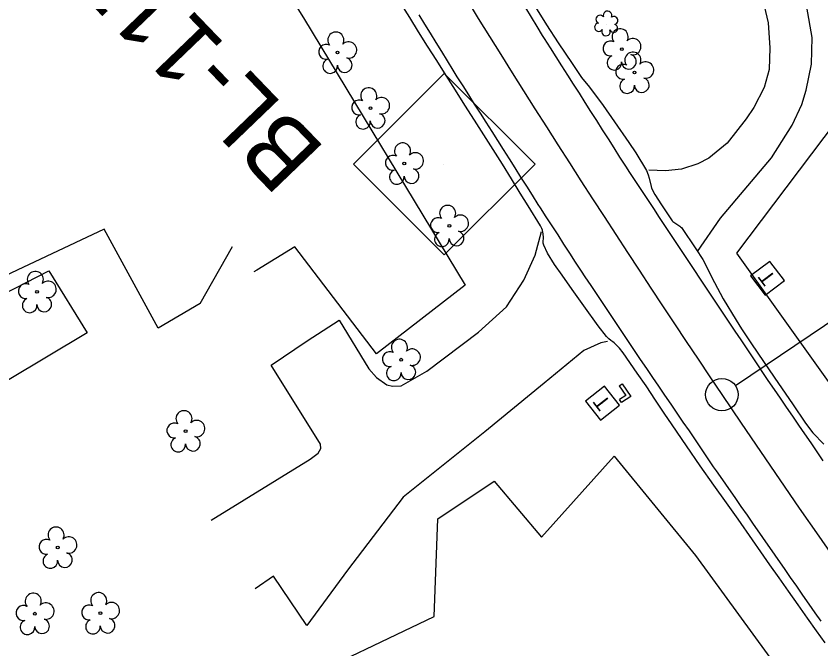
# Model space of a CAD drawing. Extents: x 474972 to 479313, y 498315 to 502691.
# Drawn here: x 476078.1 to 476264.1, y 501147 to 501293.2 of the extents above; entities that cross this region are included whole.
import ezdxf

# ---------------------------------------------------------------- set-up
doc = ezdxf.new("R2010")
doc.units = 0
for name, color, linetype in [('CTL Secondary Horizontal and Vertical CELL', 7, 'Continuous'), ('CTL Secondary Horizontal and Vertical Text', 7, 'Continuous'), ('Exist Horizontal Alignment', 7, 'Continuous'), ('Exist Other Culture Fence Line', 7, 'Continuous'), ('Exist Other Culture Gate', 7, 'Continuous'), ('Exist Roads EOP', 7, 'Continuous'), ('Exist Roads EOP Other', 7, 'Continuous'), ('Exist Roads EOT', 7, 'Continuous'), ('Exist Roads Soil', 7, 'Continuous'), ('Exist Structure Minor Head and End Wall', 7, 'Continuous'), ('Exist Utilities Telephone Pedestal CELL', 7, 'Continuous'), ('Exist Vegetation Hedge Row', 7, 'Continuous'), ('Exist Vegetation Shrub CELL', 7, 'Continuous'), ('Exist Vegetation Tree CELL', 7, 'Continuous'), ('Exist Vegetation Woods Line', 7, 'Continuous')]:
    doc.layers.add(name, color=color, linetype=linetype)

msp = doc.modelspace()

# ---------------------------------------------------------------- linework, layer by layer
at = {"layer": 'CTL Secondary Horizontal and Vertical CELL'}
msp.add_line((476176.94, 501258.94), (476176.94, 501258.94), dxfattribs=at)
msp.add_lwpolyline([(476156.08, 501259.01), (476177.05, 501279.98), (476198.05, 501258.97), (476177.08, 501238.01)], close=True, dxfattribs=at)
at = {"layer": 'Exist Horizontal Alignment'}
msp.add_line((476244.33, 501207.83), (476343.85, 501274.95), dxfattribs=at)
msp.add_circle((476241.22, 501205.74), 3.75, dxfattribs=at)
for centre, radius, start, end in [((478549.74, 502762.69), 2784.48, 207.50231, 213.99726), ((478672.62, 502845.57), 2932.7, 213.99726, 223.91157)]:
    msp.add_arc(centre, radius, start, end, dxfattribs=at)
at = {"layer": 'Exist Other Culture Fence Line'}
for points in [[(476004.79, 501280.8), (476008.93, 501283.23), (476010.34, 501284.2), (476101.32, 501347.12), (476102.6, 501347.94), (476107.45, 501351.2), (476111.31, 501345.57), (476144.53, 501292.8), (476181.9, 501231.04), (476161.39, 501215.16), (476142.53, 501239.91), (476133.73, 501234.48)], [(476120.67, 501226.83), (476110.96, 501221.14), (476098.44, 501243.97), (476039.4, 501216.16), (476004.79, 501280.8)], [(476133.73, 501234.48), (476133.1, 501234.11)]]:
    msp.add_lwpolyline(points, dxfattribs=at)
at = {"layer": 'Exist Other Culture Gate'}
msp.add_line((476120.67, 501226.83), (476128.16, 501239.99), dxfattribs=at)
at = {"layer": 'Exist Roads EOP'}
for points in [[(476265.05, 501148.38), (476263.07, 501151.18), (476260.99, 501154.11), (476258.81, 501157.2), (476256.6, 501160.33), (476254.43, 501163.4), (476252.32, 501166.42), (476250.25, 501169.39), (476248.3, 501172.19), (476244.96, 501176.94), (476242.25, 501180.77), (476239.37, 501184.83), (476236.22, 501189.3), (476233.04, 501193.91), (476229.76, 501198.74), (476227.91, 501201.49), (476225.88, 501204.49), (476223.69, 501207.74), (476221.67, 501210.73), (476218.41, 501215.44), (476217.56, 501216.45), (476216.3, 501217.73), (476216.03, 501217.95), (476215.55, 501218.28), (476215.08, 501218.67), (476214.55, 501219.2), (476212.64, 501221.62), (476209.31, 501226.25), (476206.6, 501230.07), (476204.31, 501233.32), (476202.56, 501235.81), (476200.9, 501238.4), (476200.06, 501240.27), (476199.99, 501240.48), (476199.94, 501240.72), (476199.93, 501240.98), (476199.96, 501242.07), (476199.93, 501242.9), (476199.87, 501243.31), (476199.76, 501243.73), (476199.6, 501244.17), (476199.32, 501244.73), (476196.45, 501249.4), (476194.64, 501252.33), (476192.58, 501255.64), (476190.49, 501258.98), (476188.36, 501262.35), (476186.2, 501265.76), (476184.03, 501269.19), (476181.85, 501272.62), (476179.67, 501276.06), (476177.49, 501279.51), (476175.33, 501282.93), (476173.21, 501286.3), (476171.13, 501289.6), (476169.1, 501292.85), (476167.11, 501296.06)], [(476197.73, 501295.86), (476200.71, 501291.2), (476203.42, 501287.04), (476206.59, 501282.29), (476208.75, 501279), (476210.66, 501276.76), (476213.79, 501272.53), (476216.39, 501268.8), (476219.72, 501263.97), (476221.3, 501261.6), (476223.77, 501257.51), (476224.19, 501256.56), (476224.45, 501255.73), (476224.85, 501253.8), (476224.97, 501253.45), (476225.72, 501252.02), (476227.24, 501249.57), (476229.74, 501245.91), (476229.9, 501245.75), (476230.09, 501245.59), (476231.48, 501244.68), (476231.68, 501244.51), (476231.86, 501244.34), (476235.22, 501239.47), (476236.78, 501236.97), (476239.54, 501231.69), (476241.5, 501227.86), (476244.5, 501222.94), (476245.77, 501220.97), (476247.93, 501217.71), (476251, 501213.15), (476254.28, 501208.32), (476257.5, 501203.6), (476260.56, 501199.16), (476262.24, 501196.91), (476264.74, 501194.28)]]:
    msp.add_lwpolyline(points, dxfattribs=at)
at = {"layer": 'Exist Roads EOP Other'}
for points in [[(476123.19, 501176.7), (476146.09, 501190.85), (476147.95, 501192.21), (476148.58, 501193.28), (476148.49, 501194.28), (476137.03, 501212.53), (476145.42, 501218.14), (476152.81, 501222.96), (476159.67, 501211.73), (476161.42, 501209.68), (476163.81, 501208), (476165.1, 501207.71), (476167.09, 501207.76), (476173.01, 501211.15), (476184.98, 501220.19), (476191.44, 501226), (476195.44, 501232.19), (476198.06, 501237.98), (476199.52, 501243.44)], [(476214.82, 501218.05), (476213.21, 501217.71), (476209.3, 501215.91), (476200.12, 501208.43), (476186.45, 501197.14), (476167.6, 501182.05), (476154.74, 501165.22), (476145.31, 501152.43), (476137.61, 501163.79), (476133.35, 501160.85)]]:
    msp.add_lwpolyline(points, dxfattribs=at)
at = {"layer": 'Exist Roads EOT'}
for points in [[(476264.63, 501190.47), (476263.22, 501192.54), (476261.82, 501194.6), (476260.41, 501196.66), (476259, 501198.72), (476257.59, 501200.78), (476256.18, 501202.84), (476254.77, 501204.9), (476253.36, 501206.96), (476251.95, 501209.02), (476250.55, 501211.08), (476249.82, 501212.14), (476248.44, 501214.22), (476247.05, 501216.29), (476245.66, 501218.37), (476244.27, 501220.44), (476242.88, 501222.52), (476241.5, 501224.59), (476240.11, 501226.67), (476238.72, 501228.74), (476237.33, 501230.82), (476235.94, 501232.89), (476235.09, 501234.17), (476233.71, 501236.26), (476232.34, 501238.34), (476230.96, 501240.42), (476229.59, 501242.51), (476228.21, 501244.59), (476226.84, 501246.67), (476225.46, 501248.76), (476224.09, 501250.84), (476222.71, 501252.93), (476221.34, 501255.01), (476219.96, 501257.09), (476219.01, 501258.54), (476217.67, 501260.64), (476216.33, 501262.75), (476214.99, 501264.85), (476213.65, 501266.96), (476212.31, 501269.06), (476210.96, 501271.17), (476209.62, 501273.28), (476208.28, 501275.38), (476206.94, 501277.49), (476205.6, 501279.59), (476204.26, 501281.7), (476202.92, 501283.8), (476201.58, 501285.91), (476200.24, 501288.01), (476199.8, 501288.7), (476198.5, 501290.83), (476197.2, 501292.96), (476195.89, 501295.09)], [(476264.17, 501153.38), (476262.79, 501155.31), (476261.37, 501157.36), (476259.95, 501159.41), (476258.52, 501161.46), (476257.1, 501163.51), (476255.67, 501165.57), (476254.25, 501167.62), (476252.82, 501169.67), (476251.4, 501171.72), (476249.97, 501173.77), (476248.55, 501175.82), (476247.12, 501177.87), (476245.7, 501179.92), (476244.28, 501181.97), (476242.85, 501184.02), (476241.43, 501186.07), (476240, 501188.12), (476239.32, 501189.1), (476237.92, 501191.17), (476236.51, 501193.23), (476235.1, 501195.29), (476233.7, 501197.36), (476232.29, 501199.42), (476230.89, 501201.48), (476229.48, 501203.55), (476228.07, 501205.61), (476226.67, 501207.67), (476225.26, 501209.74), (476223.86, 501211.8), (476222.45, 501213.86), (476222.13, 501214.34), (476220.74, 501216.41), (476219.35, 501218.48), (476217.96, 501220.56), (476216.57, 501222.63), (476215.18, 501224.71), (476213.79, 501226.78), (476212.4, 501228.85), (476211.01, 501230.93), (476209.62, 501233), (476208.77, 501234.26), (476207.42, 501236.36), (476206.06, 501238.46), (476204.71, 501240.55), (476203.35, 501242.65), (476202, 501244.75), (476200.64, 501246.84), (476199.29, 501248.94), (476198.79, 501249.7), (476197.46, 501251.81), (476196.12, 501253.92), (476194.78, 501256.02), (476193.45, 501258.13), (476192.11, 501260.24), (476190.77, 501262.35), (476189.43, 501264.45), (476188.1, 501266.56), (476186.76, 501268.67), (476185.42, 501270.78), (476184.08, 501272.89), (476182.75, 501274.99), (476181.41, 501277.1), (476180.07, 501279.21), (476179.1, 501280.74), (476177.79, 501282.87), (476176.49, 501285), (476175.19, 501287.13), (476173.88, 501289.26), (476172.58, 501291.38), (476171.27, 501293.51)]]:
    msp.add_lwpolyline(points, dxfattribs=at)
at = {"layer": 'Exist Roads Soil'}
for points in [[(476235.55, 501238.82), (476240.92, 501246.5), (476252.69, 501260.48), (476257.47, 501267.99), (476259.71, 501272.81), (476260.67, 501276.09), (476261.91, 501282.08), (476262.08, 501288.26), (476260.88, 501295.3), (476258.08, 501303.9), (476252.31, 501316.1), (476243.98, 501330.38), (476235.66, 501343.95), (476229.15, 501355.41), (476224.63, 501364.97), (476220.31, 501375.75), (476216.42, 501388.5), (476213.49, 501400.02), (476210.26, 501412.58), (476206.49, 501429.83), (476203.88, 501443.85)], [(476250.69, 501296.9), (476251.94, 501291.65), (476252.31, 501285.91), (476252.15, 501280.9), (476251, 501276.69), (476248.62, 501272.12), (476246.85, 501269.44), (476242.44, 501263.83), (476238.22, 501260.4), (476235.7, 501259.06), (476231.89, 501257.82), (476228.2, 501257.49), (476224.36, 501257.58)]]:
    msp.add_lwpolyline(points, dxfattribs=at)
at = {"layer": 'Exist Structure Minor Head and End Wall'}
for p, q in [((476217.52, 501207.8), (476218.21, 501208.27)), ((476218.03, 501203.91), (476217.57, 501204.61))]:
    msp.add_line(p, q, dxfattribs=at)
for points in [[(476218.21, 501208.27), (476220.18, 501205.35), (476218.03, 501203.91)], [(476217.52, 501207.8), (476219.02, 501205.57), (476217.57, 501204.61)]]:
    msp.add_lwpolyline(points, dxfattribs=at)
at = {"layer": 'Exist Utilities Telephone Pedestal CELL'}
for p, q in [((476251.8, 501232.55), (476251.8, 501232.55)), ((476213.66, 501203.7), (476213.66, 501203.7))]:
    msp.add_line(p, q, dxfattribs=at)
for points in [[(476255.7, 501232.08), (476252.33, 501236.54), (476247.86, 501233.17), (476251.24, 501228.71), (476255.7, 501232.08)], [(476217.56, 501203.28), (476214.13, 501207.7), (476209.71, 501204.27), (476213.14, 501199.85), (476217.56, 501203.28)]]:
    msp.add_lwpolyline(points, dxfattribs=at)
at = {"layer": 'Exist Vegetation Hedge Row'}
msp.add_lwpolyline([(475808.99, 501173.82), (475831, 501186.77), (475902.73, 501229.39), (475971.24, 501257.96), (476001.8, 501276.82), (476011.76, 501261.47), (476037.02, 501212.45), (476043.74, 501212.81), (476085.72, 501234.32), (476094.56, 501220.05), (476067.05, 501203.59), (476045.68, 501182.58)], dxfattribs=at)
at = {"layer": 'Exist Vegetation Shrub CELL'}
msp.add_line((476214.56, 501291.33), (476214.56, 501291.33), dxfattribs=at)
for centre, radius, start, end in [((476214.79, 501293.37), 0.99, 334.8391, 200.4717), ((476213.08, 501292.45), 0.968, 35.8908, 245.4216), ((476216.23, 501292.2), 0.929, 284.4567, 126.0861), ((476212.76, 501290.62), 0.955, 95.1099, 327.9534), ((476214.43, 501289.64), 0.984, 151.2797, 21.387), ((476216.2, 501290.4), 0.937, 204.9913, 73.4601)]:
    msp.add_arc(centre, radius, start, end, dxfattribs=at)
at = {"layer": 'Exist Vegetation Tree CELL'}
for p, q in [((476152.4, 501284.79), (476152.4, 501284.79)), ((476218.08, 501285.56), (476218.08, 501285.56)), ((476221.03, 501280.16), (476221.03, 501280.16)), ((476160.01, 501271.92), (476160.01, 501271.92)), ((476167.83, 501259.16), (476167.83, 501259.16)), ((476178.24, 501244.75), (476178.24, 501244.75)), ((476082.96, 501229.48), (476082.96, 501229.48)), ((476167.1, 501213.81), (476167.1, 501213.81)), ((476117.31, 501197.31), (476117.31, 501197.31)), ((476087.74, 501170.42), (476087.74, 501170.42)), ((476082.46, 501155.13), (476082.46, 501155.13)), ((476097.6, 501155.26), (476097.6, 501155.26))]:
    msp.add_line(p, q, dxfattribs=at)
for centre in [(476152.4, 501284.79), (476218.08, 501285.56), (476221.03, 501280.16), (476160.01, 501271.92), (476167.83, 501259.16), (476178.24, 501244.75), (476082.96, 501229.48), (476167.1, 501213.81), (476117.31, 501197.31), (476087.74, 501170.42), (476082.46, 501155.13), (476097.6, 501155.26)]:
    msp.add_circle(centre, 0.326, dxfattribs=at)
for centre, radius, start, end in [((476217.7, 501288.43), 1.86, 330.1651, 219.7134), ((476152.01, 501287.67), 1.86, 330.1651, 219.7134), ((476220.63, 501286.15), 1.9, 257.1011, 134.1999), ((476149.79, 501284.95), 1.73, 62.6636, 279.3457), ((476154.94, 501285.38), 1.9, 257.1011, 134.1999), ((476215.48, 501285.71), 1.73, 62.6636, 279.3457), ((476219.75, 501282.66), 1.7, 181.2822, 74.56), ((476220.65, 501283.03), 1.86, 330.1651, 219.7134), ((476150.69, 501281.67), 1.69, 111.5671, 6.231), ((476154.07, 501281.89), 1.7, 181.2822, 74.56), ((476216.38, 501282.44), 1.69, 111.5671, 6.231), ((476223.58, 501280.74), 1.9, 257.1011, 134.1999), ((476218.43, 501280.31), 1.73, 62.6636, 279.3457), ((476222.71, 501277.26), 1.7, 181.2822, 74.56), ((476219.33, 501277.04), 1.69, 111.5671, 6.231), ((476159.62, 501274.79), 1.86, 330.1651, 219.7134), ((476157.4, 501272.07), 1.73, 62.6636, 279.3457), ((476162.55, 501272.51), 1.9, 257.1011, 134.1999), ((476158.3, 501268.8), 1.69, 111.5671, 6.231), ((476161.68, 501269.02), 1.7, 181.2822, 74.56), ((476167.44, 501262.04), 1.86, 330.1651, 219.7134), ((476165.22, 501259.32), 1.73, 62.6636, 279.3457), ((476170.38, 501259.75), 1.9, 257.1011, 134.1999), ((476166.12, 501256.04), 1.69, 111.5671, 6.231), ((476169.5, 501256.26), 1.7, 181.2822, 74.56), ((476177.85, 501247.63), 1.86, 330.1651, 219.7134), ((476180.79, 501245.34), 1.9, 257.1011, 134.1999), ((476175.63, 501244.91), 1.73, 62.6636, 279.3457), ((476179.91, 501241.85), 1.7, 181.2822, 74.56), ((476176.53, 501241.63), 1.69, 111.5671, 6.231), ((476082.58, 501232.36), 1.86, 330.1651, 219.7134), ((476080.36, 501229.64), 1.73, 62.6636, 279.3457), ((476085.51, 501230.07), 1.9, 257.1011, 134.1999), ((476081.26, 501226.36), 1.69, 111.5671, 6.231), ((476084.64, 501226.58), 1.7, 181.2822, 74.56), ((476166.71, 501216.68), 1.86, 330.1651, 219.7134), ((476164.49, 501213.96), 1.73, 62.6636, 279.3457), ((476169.65, 501214.4), 1.9, 257.1011, 134.1999), ((476165.4, 501210.69), 1.69, 111.5671, 6.231), ((476168.77, 501210.91), 1.7, 181.2822, 74.56), ((476116.92, 501200.18), 1.86, 330.1651, 219.7134), ((476114.7, 501197.46), 1.73, 62.6636, 279.3457), ((476119.85, 501197.9), 1.9, 257.1011, 134.1999), ((476115.6, 501194.19), 1.69, 111.5671, 6.231), ((476118.98, 501194.41), 1.7, 181.2822, 74.56), ((476087.36, 501173.29), 1.86, 330.1651, 219.7134), ((476090.29, 501171), 1.9, 257.1011, 134.1999), ((476085.14, 501170.57), 1.73, 62.6636, 279.3457), ((476089.42, 501167.52), 1.7, 181.2822, 74.56), ((476086.04, 501167.3), 1.69, 111.5671, 6.231), ((476082.08, 501158.01), 1.86, 330.1651, 219.7134), ((476097.22, 501158.14), 1.86, 330.1651, 219.7134), ((476079.85, 501155.29), 1.73, 62.6636, 279.3457), ((476085.01, 501155.72), 1.9, 257.1011, 134.1999), ((476095, 501155.42), 1.73, 62.6636, 279.3457), ((476100.15, 501155.85), 1.9, 257.1011, 134.1999), ((476080.76, 501152.01), 1.69, 111.5671, 6.231), ((476084.13, 501152.23), 1.7, 181.2822, 74.56), ((476095.9, 501152.14), 1.69, 111.5671, 6.231), ((476099.28, 501152.36), 1.7, 181.2822, 74.56)]:
    msp.add_arc(centre, radius, start, end, dxfattribs=at)
at = {"layer": 'Exist Vegetation Woods Line'}
for points in [[(476279.38, 501226.11), (476269.31, 501203.89), (476244.66, 501238.47), (476270.54, 501272.71), (476270.38, 501320.15), (476294.66, 501389.95), (476291.47, 501415.35), (476249.72, 501459.42), (476238.45, 501478.55), (476264.33, 501490.35), (476280.03, 501487.66), (476286.2, 501470.43), (476297.57, 501467.02), (476303.31, 501478), (476333.64, 501481.71), (476338.14, 501502.27)], [(476120.28, 501107.83), (476141.51, 501138.59), (476174.77, 501154.51), (476175.57, 501177.07), (476188.6, 501185.75), (476199.54, 501172.78), (476216.36, 501191.55), (476235.13, 501168.55)], [(476235.13, 501168.55), (476315.23, 501058.66), (476387.51, 500964.69), (476342.8, 500890.14), (476337.73, 500880.49), (476322.46, 500861.9), (476264.16, 500837.46), (476265.8, 500863.73), (476252.8, 500862.59), (476245.69, 500852.68)]]:
    msp.add_lwpolyline(points, dxfattribs=at)

# ---------------------------------------------------------------- texts
at = {"layer": 'CTL Secondary Horizontal and Vertical Text'}
msp.add_text('BL-117', height=16, rotation=133.8723, dxfattribs=at).set_placement((476149.92, 501262.34))
at = {"layer": 'Exist Utilities Telephone Pedestal CELL'}
for rotation, p in [(127.0674, (476253.85, 501232.68)), (127.8139, (476215.71, 501203.85))]:
    msp.add_text('T', height=3.42, rotation=rotation, dxfattribs=at).set_placement(p)

doc.saveas('drawing.dxf')
